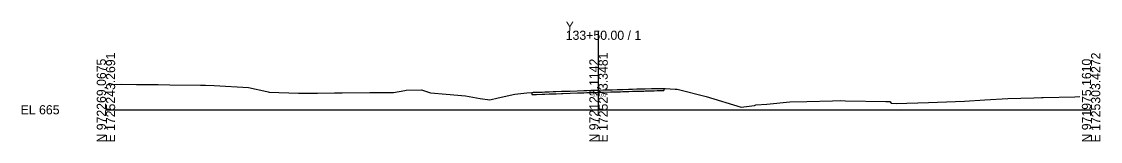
# Model space of a CAD drawing. Extents: x -26 to 1725251, y -10 to 972279.
# Drawn here: x 974.3 to 1302.8, y 7490.3 to 7527 of the extents above; entities that cross this region are included whole.
import ezdxf

# ---------------------------------------------------------------- set-up
doc = ezdxf.new("R2010")
doc.units = 0
for name, color, linetype in [('Default', 7, 'Continuous'), ('Exist Cross Section Cell', 7, 'Continuous'), ('Exist XS Center Line Elevation Label', 7, 'Continuous'), ('Exist XS Ground Line', 7, 'Continuous')]:
    doc.layers.add(name, color=color, linetype=linetype)

msp = doc.modelspace()

# ---------------------------------------------------------------- linework, layer by layer
at = {"layer": 'Exist Cross Section Cell'}
for p, q in [((1150, 7500), (1150, 7524.17)), ((1000, 7500), (1150, 7500)), ((1150, 7500), (1300, 7500))]:
    msp.add_line(p, q, dxfattribs=at)
at = {"layer": 'Exist XS Ground Line'}
for p, q in [((1129.71, 7505.31), (1129.71, 7504.64)), ((1169.84, 7506.54), (1169.84, 7505.88))]:
    msp.add_line(p, q, dxfattribs=at)
for points in [[(1000.73, 7508.06), (1001.25, 7508.02), (1002.24, 7507.72), (1004.88, 7507.82), (1009.27, 7507.75), (1015.94, 7507.68), (1019.48, 7507.64), (1028.77, 7507.55), (1029.69, 7507.54), (1030.29, 7507.52), (1032.94, 7507.37), (1043.38, 7506.79), (1049.03, 7505.55), (1049.36, 7505.48), (1049.68, 7505.43), (1058.6, 7505.12), (1061.91, 7505.1), (1064.39, 7505.1), (1069.64, 7505.13), (1071.95, 7505.13), (1080.35, 7505.3), (1080.79, 7505.3), (1081.1, 7505.3), (1082.56, 7505.3), (1087.55, 7505.28), (1091, 7505.87), (1091.43, 7505.95), (1096.1, 7506.14), (1098.85, 7505.21), (1103.62, 7504.79), (1109.48, 7504.23), (1114, 7503.46), (1116.94, 7503.04), (1119.47, 7503.63), (1124.48, 7504.8), (1128.19, 7505.14), (1129.71, 7505.31), (1130.05, 7505.33), (1130.73, 7505.36), (1131.06, 7505.37), (1132.81, 7505.43), (1133.66, 7505.46), (1134.94, 7505.5), (1136.2, 7505.54), (1137.05, 7505.59), (1138.73, 7505.67), (1139.16, 7505.68), (1141.31, 7505.73), (1143.54, 7505.82), (1145.51, 7505.89), (1146.39, 7505.92), (1147.68, 7505.95), (1148.86, 7505.98), (1149.69, 7506), (1150, 7506.01), (1151.49, 7506.06), (1153.68, 7506.12), (1154.13, 7506.13), (1155.67, 7506.17), (1156.24, 7506.19), (1156.63, 7506.2), (1157.39, 7506.22), (1159.16, 7506.28), (1160.34, 7506.32), (1161.68, 7506.36), (1163.74, 7506.4), (1164.23, 7506.41), (1166.1, 7506.47), (1166.97, 7506.5), (1167.85, 7506.52), (1168.5, 7506.53), (1169.84, 7506.54), (1170.29, 7506.54), (1173.37, 7506.3), (1173.94, 7506.25), (1182.8, 7504.02), (1193.39, 7500.75), (1197.46, 7501.35), (1197.95, 7501.49), (1201.29, 7501.72), (1208.22, 7502.45), (1213.41, 7502.54), (1221.27, 7502.72), (1223.62, 7502.81), (1225.16, 7502.78), (1237.46, 7502.49), (1238.7, 7502.48), (1239.12, 7501.98), (1240.62, 7501.96), (1250.52, 7502.25), (1261.42, 7502.66), (1267.63, 7502.99), (1274.65, 7503.4), (1282.58, 7503.64), (1284.86, 7503.72), (1285.44, 7503.74), (1295.06, 7504), (1296.53, 7504.02)], [(1129.71, 7504.64), (1130.08, 7504.66), (1130.76, 7504.69), (1131.08, 7504.71), (1132.83, 7504.77), (1133.68, 7504.79), (1134.96, 7504.83), (1136.23, 7504.87), (1137.08, 7504.92), (1138.76, 7505), (1139.18, 7505.01), (1141.33, 7505.06), (1143.57, 7505.15), (1145.53, 7505.22), (1146.41, 7505.25), (1147.7, 7505.28), (1148.88, 7505.31), (1149.71, 7505.34), (1150.02, 7505.35), (1151.51, 7505.4), (1153.7, 7505.46), (1154.14, 7505.47), (1155.68, 7505.5), (1156.26, 7505.52), (1156.65, 7505.53), (1157.41, 7505.56), (1159.18, 7505.61), (1160.36, 7505.65), (1161.69, 7505.7), (1163.75, 7505.73), (1164.25, 7505.74), (1166.12, 7505.81), (1166.99, 7505.83), (1167.86, 7505.85), (1168.51, 7505.86), (1169.84, 7505.88)]]:
    msp.add_lwpolyline(points, dxfattribs=at)

# ---------------------------------------------------------------- texts
at = {"layer": 'Default'}
msp.add_text('-', height=0.0001, dxfattribs=at).set_placement((1000, 7500))
at = {"layer": 'Exist Cross Section Cell'}
for s, p in [('Y', (1140, 7524.17)), ('133+50.00 / 1', (1140, 7521.37)), ('EL 665', (974, 7498.6))]:
    msp.add_text(s, height=2.8, dxfattribs=at).set_placement(p)
for s, p in [('E 1725243.2691', (1002.8, 7490)), ('E 1725273.3481', (1152.8, 7490)), ('E 1725303.4272', (1302.8, 7490)), ('N 972269.0675', (1000, 7490)), ('N 972122.1142', (1150, 7490)), ('N 971975.1610', (1300, 7490))]:
    msp.add_text(s, height=2.8, rotation=90, dxfattribs=at).set_placement(p)
at = {"layer": 'Exist XS Center Line Elevation Label'}
msp.add_text('671.01', height=1, dxfattribs=at).set_placement((1148.15, 7504.06))

doc.saveas('drawing.dxf')
